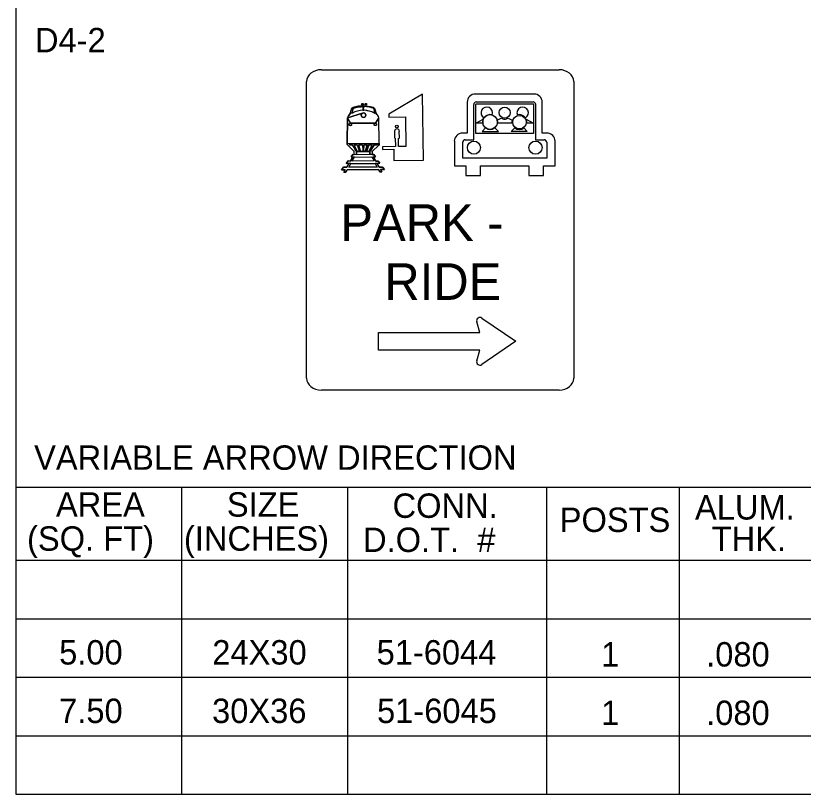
# Model space of a CAD drawing. Extents: x 0 to 2011, y -71 to 1183.
# Drawn here: x 214.5 to 317.8, y 496.8 to 598.9 of the extents above; entities that cross this region are included whole.
import ezdxf

# ---------------------------------------------------------------- set-up
doc = ezdxf.new("R2010")
doc.units = 0
for name, color, linetype in [('Level 1', 7, 'Continuous'), ('Level 2', 7, 'Continuous'), ('Level 5', 7, 'Continuous')]:
    doc.layers.add(name, color=color, linetype=linetype)

msp = doc.modelspace()

# ---------------------------------------------------------------- linework, layer by layer
at = {"layer": 'Level 1'}
for p, q in [((254.62, 591.8), (285.78, 591.8)), ((252.69, 551.35), (252.69, 590.26)), ((287.71, 590.26), (287.71, 551.35)), ((278.66, 588.62), (274.8, 588.62)), ((282.51, 588.62), (278.66, 588.62)), ((273.75, 587.56), (273.75, 583.49)), ((274.93, 587.58), (278.66, 587.58)), ((278.66, 587.58), (282.39, 587.58)), ((283.57, 583.49), (283.57, 587.56)), ((258.39, 586.09), (258.56, 586.65)), ((260.1, 586.55), (260.1, 586.87)), ((260.17, 586.55), (260.16, 586.87)), ((261.81, 586.08), (261.64, 586.65)), ((274.59, 582.62), (274.59, 587.26)), ((274.86, 583.44), (274.86, 587.26)), ((274.93, 587.32), (278.66, 587.32)), ((278.66, 587.32), (282.39, 587.32)), ((282.45, 587.26), (282.45, 583.44)), ((282.71, 587.26), (282.71, 582.62)), ((277.67, 585.19), (278.21, 585.46)), ((279.1, 585.46), (279.63, 585.19)), ((274.86, 584.78), (275.84, 585.32)), ((275.78, 584.78), (274.86, 584.78)), ((278.66, 584.78), (277.69, 584.78)), ((279.62, 584.78), (278.66, 584.78)), ((279.62, 584.78), (279.62, 584.78)), ((281.47, 585.32), (282.45, 584.78)), ((282.45, 584.78), (281.53, 584.78)), ((273.75, 583.49), (273.12, 583.49)), ((278.66, 583.44), (274.86, 583.44)), ((276.15, 584.18), (275.69, 583.7)), ((275.69, 583.7), (277.83, 583.7)), ((277.83, 583.7), (277.34, 584.19)), ((282.45, 583.44), (278.66, 583.44)), ((279.49, 583.7), (279.97, 584.19)), ((281.62, 583.7), (279.49, 583.7)), ((281.16, 584.18), (281.62, 583.7)), ((284.2, 583.49), (283.57, 583.49)), ((272.06, 582.44), (272.06, 579.2)), ((273.48, 582.62), (274.59, 582.62)), ((282.71, 582.62), (283.83, 582.62)), ((285.25, 579.2), (285.25, 582.44)), ((261.32, 581.14), (262.11, 581.89)), ((273.15, 580.22), (273.15, 582.29)), ((284.16, 582.29), (284.16, 580.22)), ((261.27, 581.01), (261.29, 581.07)), ((261.29, 581.07), (261.32, 581.14)), ((278.66, 580.22), (273.15, 580.22)), ((284.16, 580.22), (278.66, 580.22)), ((257.81, 578.37), (257.57, 578.37)), ((272.06, 579.2), (273.56, 579.2)), ((273.56, 579.2), (273.56, 577.93)), ((275.48, 577.93), (275.48, 579.2)), ((275.48, 579.2), (278.66, 579.2)), ((278.66, 579.2), (281.83, 579.2)), ((281.83, 579.2), (281.83, 577.93)), ((283.75, 577.93), (283.75, 579.2)), ((283.75, 579.2), (285.25, 579.2)), ((273.56, 577.93), (275.48, 577.93)), ((281.83, 577.93), (283.75, 577.93)), ((275.41, 557.37), (274.99, 558.75)), ((275.67, 559.25), (280.11, 556.2)), ((262.11, 555.03), (262.11, 557.37)), ((262.11, 557.37), (275.41, 557.37)), ((280.11, 556.2), (275.67, 553.16)), ((280.11, 556.2), (280.11, 556.2)), ((275.41, 555.03), (262.11, 555.03)), ((274.99, 553.65), (275.41, 555.03)), ((252.69, 551.35), (252.69, 551.35)), ((285.78, 549.8), (254.62, 549.8))]:
    msp.add_line(p, q, dxfattribs=at)
for points in [[(267.99, 579.96), (267.88, 588.59), (263.47, 585.97), (263.46, 585.6), (265.67, 585.61), (265.7, 581.73), (264.72, 581.73), (264.75, 582.81)], [(258, 582.16), (258.03, 585.51)], [(262.2, 582.15), (262.17, 585.5)], [(264.21, 583.75), (264.2, 582.91)], [(264.85, 582.9), (264.84, 583.73)], [(264.3, 582.83), (264.34, 581.74), (262.64, 581.71), (262.64, 581.37), (264.13, 581.39), (264.14, 579.92), (267.99, 579.96)], [(257.57, 578.37), (257.76, 578.69), (257.24, 578.7), (257.51, 579.05), (257.97, 579.05), (258.23, 579.53), (257.88, 579.53), (258.12, 579.85), (258.44, 579.84), (258.72, 580.37), (258.51, 580.37), (258.73, 580.68), (258.87, 580.68), (258.92, 580.68), (258.93, 581.02), (258.92, 581.08), (258.88, 581.15), (258.09, 581.9)], [(258.3, 582.13), (261.92, 582.14), (261.92, 581.96), (261.55, 581.96)], [(258.3, 582.13), (258.3, 581.94), (258.67, 581.95)], [(258.67, 581.95), (259.15, 581.18), (259.32, 581.18), (258.93, 581.95)], [(259.31, 581.95), (258.93, 581.95)], [(259.31, 581.95), (259.56, 581.19), (259.74, 581.19), (259.53, 581.95)], [(260.02, 581.95), (259.53, 581.95)], [(260.02, 581.95), (260.04, 581.18), (260.2, 581.18), (260.22, 581.95)], [(260.63, 581.95), (260.22, 581.95)], [(260.85, 581.96), (260.6, 581.18), (260.42, 581.18), (260.63, 581.95)], [(261.29, 581.96), (260.85, 581.96)], [(261.55, 581.96), (261.07, 581.19), (260.9, 581.19), (261.29, 581.96)], [(261.27, 581.01), (261.27, 580.68), (261.5, 580.68), (261.7, 580.38), (261.46, 580.38), (261.74, 579.84), (262.08, 579.84), (262.29, 579.55), (261.93, 579.53), (262.19, 579.04), (262.65, 579.05), (262.88, 578.71), (262.37, 578.71), (262.53, 578.4), (262.29, 578.4), (262.12, 578.71), (257.99, 578.7), (257.81, 578.37)], [(258.93, 580.36), (261.22, 580.39), (261.53, 579.85), (258.62, 579.84), (258.95, 580.36)], [(259.23, 581.07), (260.98, 581.08), (260.99, 580.68), (259.23, 580.67), (259.23, 581.07)], [(258.46, 579.52), (261.68, 579.53), (261.93, 579.05), (258.2, 579.05), (258.48, 579.51)]]:
    msp.add_lwpolyline(points, dxfattribs=at)
for points in [[(262.17, 585.5), (262.12, 585.67), (262, 585.8), (261.88, 585.93), (261.81, 586.08), (261.61, 586.12), (261.57, 586.13), (261.22, 586.29), (260.91, 586.39), (260.64, 586.44), (260.49, 586.47), (260.2, 586.5), (260.06, 586.5), (259.71, 586.47), (259.36, 586.39), (259, 586.27), (258.69, 586.13), (258.39, 586.09), (258.32, 585.94), (258.2, 585.81), (258.08, 585.68), (258.03, 585.51), (260, 586.11), (260, 586.11), (259.94, 586.06), (259.89, 586), (259.85, 585.85), (259.89, 585.7), (259.94, 585.64), (260, 585.59), (260.15, 585.55), (260.3, 585.59), (260.36, 585.64), (260.41, 585.7), (260.45, 585.85), (260.41, 586), (260.36, 586.06), (260.3, 586.11), (260.15, 586.15), (260.03, 586.12), (260, 586.11), (258.03, 585.51), (258.42, 584.78), (261.7, 584.8)], [(258.39, 586.09), (258.56, 586.65), (258.66, 586.78), (258.81, 586.85), (258.86, 586.76), (258.77, 586.7), (258.73, 586.61), (258.63, 586.15), (258.63, 586.15), (258.65, 586.12)], [(258.81, 586.85), (258.86, 586.76), (259.12, 586.84), (259.33, 586.9), (259.61, 586.95), (259.83, 586.96), (259.95, 586.97), (260.02, 586.96), (260.05, 586.93), (260.09, 586.88), (260.1, 586.87), (260.1, 586.55), (260.09, 586.52), (260.06, 586.49), (260.2, 586.5), (260.17, 586.52), (260.17, 586.55), (260.16, 586.87), (260.21, 586.93), (260.31, 586.97), (260.1, 587.06), (260.1, 587.06), (259.91, 587.06), (259.71, 587.04), (259.49, 587.01), (259.28, 586.98), (259.08, 586.93), (258.91, 586.88)], [(261.81, 586.08), (261.61, 586.12), (261.64, 586.15), (261.64, 586.15), (261.6, 586.38), (261.53, 586.61), (261.49, 586.7), (261.4, 586.76), (261.2, 586.83), (260.98, 586.89), (260.77, 586.93), (260.53, 586.96), (260.31, 586.97), (260.1, 587.06), (260.34, 587.05), (260.54, 587.03), (260.84, 586.99), (261.17, 586.92), (261.37, 586.85), (261.39, 586.84), (261.5, 586.8), (261.57, 586.74), (261.62, 586.67), (261.64, 586.65)], [(258, 582.16), (262.2, 582.15), (262.17, 585.5), (261.7, 584.8), (261.78, 584.78), (261.83, 584.72), (261.86, 584.64), (261.83, 584.56), (261.78, 584.5), (261.7, 584.48), (261.62, 584.5), (261.56, 584.56), (261.54, 584.64), (261.56, 584.72), (261.62, 584.78), (261.7, 584.8), (258.42, 584.78), (258.5, 584.76), (258.56, 584.7), (258.58, 584.62), (258.56, 584.54), (258.5, 584.48), (258.42, 584.46), (258.34, 584.48), (258.28, 584.54), (258.26, 584.62), (258.28, 584.7), (258.34, 584.76), (258.42, 584.78), (258.03, 585.51)], [(262.2, 582.15), (262.18, 581.99), (262.1, 581.89), (261.32, 581.14), (261.3, 581.08), (261.28, 581.04), (261.27, 580.68), (260.99, 580.68), (260.98, 581.08), (259.23, 581.07), (259.23, 580.67), (258.92, 580.68), (258.93, 581.02), (258.9, 581.1), (258.87, 581.16), (258.88, 581.15), (258.09, 581.9), (258.02, 582.02), (258, 582.16), (258.3, 582.13), (258.3, 581.94), (258.67, 581.95), (259.15, 581.18), (259.32, 581.18), (258.93, 581.95), (259.31, 581.95), (259.56, 581.19), (259.74, 581.19), (259.53, 581.95), (260.02, 581.95), (260.04, 581.18), (260.2, 581.18), (260.22, 581.95), (260.63, 581.95), (260.42, 581.18), (260.6, 581.18), (260.85, 581.96), (261.29, 581.96), (260.9, 581.19), (261.07, 581.19), (261.55, 581.96), (261.92, 581.96), (261.92, 582.14)], [(257.88, 579.53), (262.29, 579.55), (262.08, 579.84), (261.74, 579.84), (261.46, 580.38), (261.7, 580.38), (261.5, 580.68), (261.27, 580.68), (260.99, 580.68), (259.23, 580.67), (258.73, 580.68), (258.51, 580.37), (258.72, 580.37), (258.93, 580.36), (261.22, 580.39), (261.53, 579.85), (258.62, 579.84), (258.95, 580.36), (258.72, 580.37), (258.44, 579.84), (258.12, 579.85)], [(257.51, 579.05), (257.24, 578.7), (257.76, 578.69), (257.57, 578.37), (257.81, 578.37), (257.99, 578.7), (262.12, 578.71), (262.29, 578.4), (262.53, 578.4), (262.37, 578.71), (262.88, 578.71), (262.65, 579.05), (262.19, 579.04), (261.93, 579.53), (261.68, 579.53), (261.93, 579.05), (258.2, 579.05), (258.48, 579.51), (258.23, 579.53), (257.97, 579.05)]]:
    msp.add_lwpolyline(points, close=True, dxfattribs=at)
for centre, radius in [((260, 587.28), 0.121), ((260.43, 587.28), 0.121), ((278.66, 586.18), 0.724), ((260.15, 585.85), 0.298), ((276.74, 584.95), 0.971), ((280.59, 584.93), 0.89), ((258.42, 584.62), 0.159), ((261.7, 584.64), 0.159), ((264.52, 584.35), 0.178), ((274.62, 581.59), 0.855), ((282.69, 581.59), 0.861)]:
    msp.add_circle(centre, radius, dxfattribs=at)
for centre, radius, start, end in [((274.8, 587.56), 1.06, 89.9998, 180), ((282.51, 587.56), 1.06, 360, 90.0002), ((274.93, 587.25), 0.33, 90, 179.9999), ((282.39, 587.25), 0.33, 0.0001, 90), ((258.9, 586.48), 0.38, 104.4029, 153.5069), ((260.75, 585.9), 2.14, 160.8398, 173.2704), ((260.23, 583.13), 3.38, 92.9416, 117.1252), ((258.91, 586.59), 0.178, 103.6949, 173.6857), ((260.09, 583.01), 4.05, 71.1878, 108.433), ((260, 583.84), 3.13, 90.8903, 111.1999), ((259.96, 586.82), 0.15, 19.0492, 93.9205), ((260.05, 586.55), 0.0513, 283.9226, 2.456), ((260.3, 586.82), 0.15, 86.0795, 160.9508), ((260.22, 586.55), 0.0513, 177.544, 256.0774), ((260.03, 583.13), 3.38, 62.8748, 87.0584), ((260.27, 583.84), 3.13, 68.8001, 89.1097), ((261.3, 586.48), 0.38, 26.4931, 75.5971), ((261.36, 586.59), 0.178, 6.3143, 76.3051), ((259.51, 585.9), 2.14, 6.7296, 19.1602), ((274.93, 587.25), 0.066, 90, 179.9999), ((276.3, 586.17), 0.747, 338.1694, 241.5129), ((281.01, 586.17), 0.747, 298.4871, 201.8306), ((282.39, 587.25), 0.066, 0.0001, 90), ((258.45, 585.47), 0.424, 126.0727, 174.8195), ((257.87, 586.23), 0.534, 308.031, 344.3003), ((258.66, 586.16), 0.0381, 182.8654, 318.1939), ((261.6, 586.16), 0.0381, 221.806, 357.1346), ((262.33, 586.22), 0.534, 195.6997, 231.969), ((261.75, 585.46), 0.424, 5.1805, 53.9273), ((276.74, 584.95), 0.971, 74.7837, 144.8973), ((278.66, 586.18), 0.851, 237.9547, 269.8201), ((278.65, 586.18), 0.851, 270.1799, 302.0453), ((280.58, 584.95), 0.971, 35.1027, 105.2163), ((276.74, 584.95), 0.971, 157.7423, 190.3083), ((276.74, 584.95), 0.971, 349.691, 14.3149), ((280.58, 584.95), 0.971, 165.6851, 190.309), ((280.58, 584.95), 0.971, 349.6917, 22.2577), ((264.53, 583.74), 0.319, 357.9657, 179.6228), ((273.11, 582.44), 1.06, 89.9992, 180), ((276.74, 584.95), 0.971, 232.6583, 308.4346), ((280.58, 584.95), 0.971, 231.5654, 307.3417), ((284.2, 582.44), 1.06, 360, 90.0008), ((264.31, 582.93), 0.108, 191.7388, 264.7446), ((264.74, 582.92), 0.108, 275.2554, 348.2612), ((273.48, 582.29), 0.33, 89.9998, 180), ((283.83, 582.29), 0.33, 360, 90.0002), ((258.38, 582.15), 0.38, 179.499, 221.231), ((261.82, 582.14), 0.38, 318.769, 0.501), ((275.42, 558.88), 0.446, 55.5114, 196.6409), ((275.42, 553.52), 0.446, 163.3591, 304.4886)]:
    msp.add_arc(centre, radius, start, end, dxfattribs=at)
for centre, major_axis, start_param, end_param in [((254.62, 590.26), (-1.93, 0), 4.712389, 6.283185), ((285.78, 590.26), (1.93, 0), 0, 1.570796), ((254.62, 551.35), (-1.93, 0), 0, 1.570796), ((285.78, 551.35), (1.93, 0), 4.712389, 6.283185)]:
    msp.add_ellipse(centre, major_axis=major_axis, ratio=0.8, start_param=start_param, end_param=end_param, dxfattribs=at)
at = {"layer": 'Level 2'}
for p, q in [((276.3, 586.17), (276.3, 586.17)), ((278.65, 586.18), (278.65, 586.18)), ((278.66, 586.18), (278.66, 586.18)), ((281.01, 586.17), (281.01, 586.17)), ((276.74, 584.95), (276.74, 584.95)), ((280.57, 584.95), (280.57, 584.95)), ((214.55, 537.09), (319.3, 537.09)), ((236.3, 537.09), (236.3, 496.81)), ((258.05, 537.09), (258.05, 496.81)), ((284.15, 537.09), (284.15, 496.81)), ((301.55, 537.09), (301.55, 496.81)), ((214.55, 527.5), (319.3, 527.5)), ((214.55, 519.83), (319.3, 519.83)), ((214.55, 512.16), (319.3, 512.16)), ((214.55, 504.48), (319.3, 504.48))]:
    msp.add_line(p, q, dxfattribs=at)
msp.add_lwpolyline([(319.3, 600.44), (214.55, 600.44), (214.55, 496.81), (319.3, 496.81)], close=True, dxfattribs=at)
at = {"layer": 'Level 5'}
msp.add_line((214.55, 830), (214.55, 496.81), dxfattribs=at)

# ---------------------------------------------------------------- texts
at = {"layer": 'Level 2'}
for s, height, p in [('D4-2', 3.2, (217.07, 594.09)), ('PARK -', 4.8, (257.11, 569.37)), ('RIDE', 4.8, (262.87, 561.63)), ('VARIABLE ARROW DIRECTION', 3.2, (216.96, 539.35)), ('AREA', 3.2, (219.82, 533.21)), ('SIZE', 3.2, (242.23, 533.21)), ('CONN.', 3.2, (263.95, 533.05)), ('ALUM.', 3.2, (303.61, 532.83)), ('POSTS', 3.2, (285.87, 531.2)), ('(SQ. FT)', 3.2, (216.03, 528.74)), ('(INCHES)', 3.2, (236.6, 528.74)), ('D.O.T.  #', 3.2, (260.08, 528.58)), ('THK.', 3.2, (305.79, 528.69))]:
    msp.add_text(s, height=height, dxfattribs=at).set_placement(p)
at = {"layer": 'Level 5'}
for s, p in [(' 5.00', (219.05, 513.82)), ('24X30', (240.32, 513.82)), ('51-6044', (261.86, 513.82)), ('1', (291.29, 513.56)), ('.080', (305.07, 513.56)), (' 7.50', (219.05, 506.15)), ('30X36', (240.29, 506.15)), ('51-6045', (261.92, 506.15)), ('1', (291.29, 505.89)), ('.080', (305.07, 505.89))]:
    msp.add_text(s, height=3.2, dxfattribs=at).set_placement(p)

doc.saveas('drawing.dxf')
